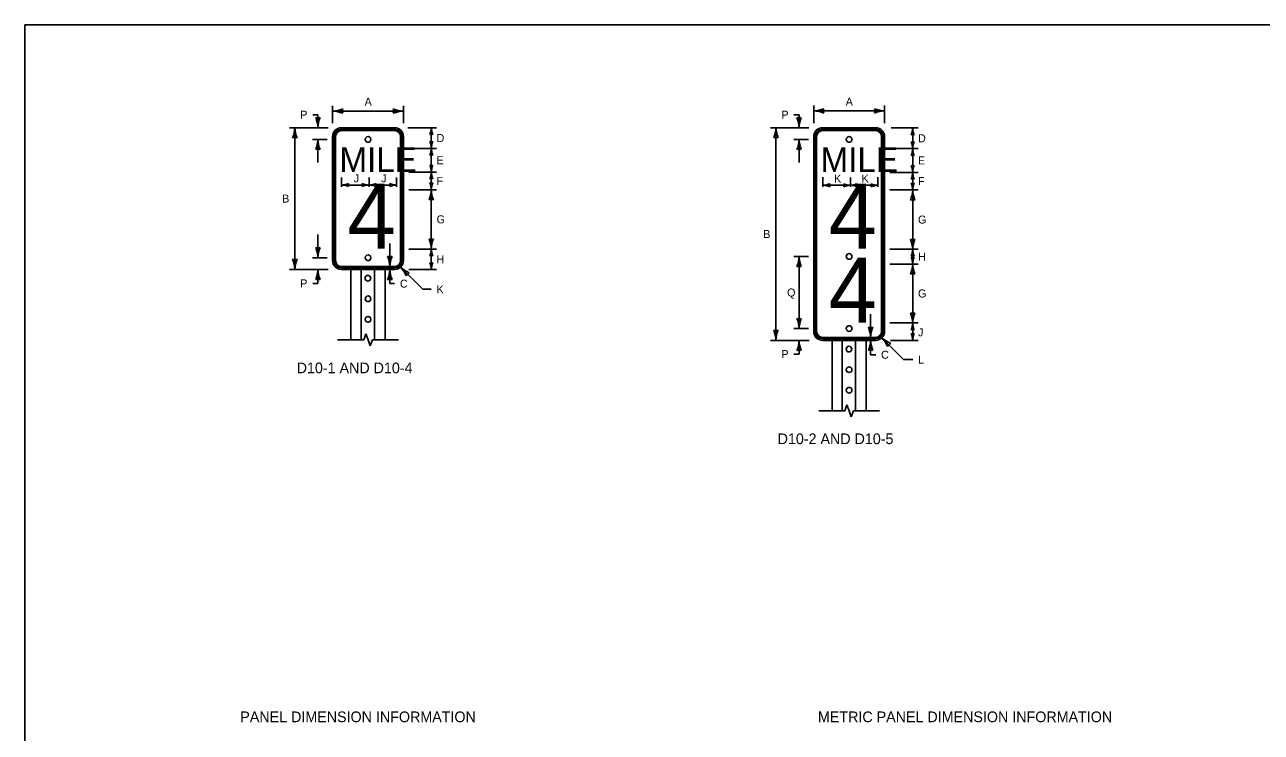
# Model space of a CAD drawing. Extents: x 49991.4 to 50021, y 49987.6 to 50011.4.
# Drawn here: x 49999.38 to 50008.65, y 49993.7 to 49999 of the extents above; entities that cross this region are included whole.
import ezdxf

# ---------------------------------------------------------------- set-up
doc = ezdxf.new("R2010")
doc.units = 0
for name, color, linetype in [('Default', 7, 'Continuous'), ('Level 1', 7, 'Continuous'), ('Level 2', 7, 'Continuous'), ('Level 3', 7, 'Continuous'), ('Level 6', 7, 'Continuous')]:
    doc.layers.add(name, color=color, linetype=linetype)

msp = doc.modelspace()

# ---------------------------------------------------------------- linework, layer by layer
at = {"layer": 'Default'}
msp.add_line((50005.8072, 49996.6522), (50005.8072, 49996.6522), dxfattribs=at)
at = {"layer": 'Level 1'}
for p, q in [((50001.6909, 49998.1614), (50001.6909, 49997.2318)), ((50001.7019, 49998.1614), (50001.7019, 49997.2318)), ((50001.713, 49998.1614), (50001.713, 49997.2318)), ((50001.7573, 49998.2278), (50002.1557, 49998.2278)), ((50002.1557, 49998.2167), (50001.7573, 49998.2167)), ((50002.1557, 49998.2057), (50001.7573, 49998.2057)), ((50002.1999, 49997.2318), (50002.1999, 49998.1614)), ((50002.211, 49997.2318), (50002.211, 49998.1614)), ((50002.2221, 49997.2318), (50002.2221, 49998.1614)), ((50005.2969, 49998.1614), (50005.2969, 49996.7006)), ((50005.308, 49998.1614), (50005.308, 49996.7006)), ((50005.319, 49996.7005), (50005.319, 49998.1614)), ((50005.7617, 49998.2278), (50005.3633, 49998.2278)), ((50005.7617, 49998.2168), (50005.3633, 49998.2168)), ((50005.3633, 49998.2056), (50005.7617, 49998.2056)), ((50005.806, 49998.1614), (50005.806, 49996.7005)), ((50005.817, 49996.7006), (50005.817, 49998.1614)), ((50005.8281, 49996.7006), (50005.8281, 49998.1614)), ((50001.7573, 49997.1875), (50002.1557, 49997.1875)), ((50001.7573, 49997.1764), (50002.1557, 49997.1764)), ((50001.7573, 49997.1654), (50002.1557, 49997.1654)), ((50001.8287, 49997.1654), (50001.8287, 49996.6377)), ((50001.9044, 49997.1654), (50001.9044, 49996.6377)), ((50002.0049, 49997.1654), (50002.0049, 49996.6377)), ((50002.0841, 49997.1654), (50002.0841, 49996.6377)), ((50005.7617, 49996.6563), (50005.3633, 49996.6563)), ((50005.3633, 49996.6453), (50005.7617, 49996.6453)), ((50005.3633, 49996.6342), (50005.7617, 49996.6342)), ((50005.4347, 49996.6342), (50005.4347, 49996.1065)), ((50005.5104, 49996.6342), (50005.5104, 49996.1065)), ((50005.6109, 49996.6342), (50005.6109, 49996.1065)), ((50005.6901, 49996.6342), (50005.6901, 49996.1065))]:
    msp.add_line(p, q, dxfattribs=at)
msp.add_lwpolyline([(49999.3835, 49998.9992), (50016.7501, 49998.9992), (50016.7501, 49987.7988), (49999.3835, 49987.7988)], close=True, dxfattribs=at)
for centre in [(50001.9564, 49998.1397), (50005.5624, 49998.1397), (50001.9564, 49997.2533), (50005.5624, 49997.2626), (50001.9552, 49997.0997), (50001.9564, 49996.9455), (50001.9564, 49996.7916), (50005.5625, 49996.7222), (50005.5612, 49996.5685), (50005.5624, 49996.4143), (50005.5624, 49996.2604)]:
    msp.add_circle(centre, 0.0213, dxfattribs=at)
for centre, radius, start, end in [((50001.7573, 49998.1614), 0.0664, 90, 180), ((50001.7573, 49998.1614), 0.0553, 90, 180), ((50001.7573, 49998.1614), 0.0443, 90, 180), ((50002.1557, 49998.1614), 0.0664, 0, 90), ((50002.1557, 49998.1614), 0.0553, 0, 90), ((50002.1557, 49998.1614), 0.0443, 0, 90), ((50005.3633, 49998.1614), 0.0664, 90, 180), ((50005.3633, 49998.1614), 0.0553, 90, 180), ((50005.3633, 49998.1614), 0.0443, 90, 180), ((50005.7617, 49998.1614), 0.0664, 0, 90), ((50005.7617, 49998.1614), 0.0553, 0, 90), ((50005.7617, 49998.1614), 0.0443, 0, 90), ((50001.7573, 49997.2318), 0.0664, 180, 270), ((50001.7573, 49997.2318), 0.0553, 180, 270), ((50001.7573, 49997.2318), 0.0443, 180, 270), ((50002.1557, 49997.2318), 0.0664, 270, 0), ((50002.1557, 49997.2318), 0.0553, 270, 0), ((50002.1557, 49997.2318), 0.0443, 270, 0), ((50005.3633, 49996.7006), 0.0664, 180, 270), ((50005.3633, 49996.7006), 0.0553, 180, 270), ((50005.3633, 49996.7006), 0.0443, 180, 270), ((50005.7617, 49996.7006), 0.0664, 270, 0), ((50005.7617, 49996.7006), 0.0553, 270, 0), ((50005.7617, 49996.7006), 0.0443, 270, 0)]:
    msp.add_arc(centre, radius, start, end, dxfattribs=at)
at = {"layer": 'Level 2'}
for p, q in [((50006.0386, 49998.226), (50006.0386, 49998.0708)), ((50006.0386, 49998.0708), (50006.0386, 49997.8931))]:
    msp.add_line(p, q, dxfattribs=at)
at = {"layer": 'Level 3'}
for p, q in [((50001.6908, 49998.2614), (50001.6908, 49998.3925)), ((50001.6908, 49998.3525), (50002.2221, 49998.3525)), ((50002.2221, 49998.2614), (50002.2221, 49998.3925)), ((50005.2969, 49998.2614), (50005.2969, 49998.3933)), ((50005.2969, 49998.3533), (50005.8281, 49998.3533)), ((50005.8281, 49998.2614), (50005.8281, 49998.3933)), ((50001.581, 49998.325), (50001.5423, 49998.325)), ((50001.581, 49998.325), (50001.581, 49998.2277)), ((50005.187, 49998.325), (50005.1483, 49998.325)), ((50005.187, 49998.325), (50005.187, 49998.2277)), ((50001.3681, 49998.2277), (50001.6573, 49998.2277)), ((50001.4081, 49998.2277), (50001.4081, 49997.1653)), ((50002.2557, 49998.2277), (50002.4705, 49998.2277)), ((50002.4305, 49998.2277), (50002.4305, 49998.0725)), ((50004.9741, 49998.2277), (50005.2593, 49998.2277)), ((50005.0141, 49998.2277), (50005.0141, 49996.6341)), ((50005.8771, 49998.226), (50006.0786, 49998.226)), ((50001.541, 49998.1397), (50001.6508, 49998.1397)), ((50001.581, 49998.1397), (50001.581, 49997.9663)), ((50002.2621, 49998.0725), (50002.4705, 49998.0725)), ((50002.4305, 49998.0725), (50002.4305, 49997.8948)), ((50005.147, 49998.1397), (50005.2569, 49998.1397)), ((50005.187, 49998.1397), (50005.187, 49997.9663)), ((50005.8681, 49998.0708), (50006.0786, 49998.0708)), ((50002.2621, 49997.8948), (50002.4705, 49997.8948)), ((50002.4305, 49997.8948), (50002.4305, 49997.7629)), ((50005.8681, 49997.8931), (50006.0786, 49997.8931)), ((50006.0386, 49997.8931), (50006.0386, 49997.7612)), ((50001.7582, 49997.8557), (50001.7582, 49997.7856)), ((50001.7582, 49997.7981), (50001.9813, 49997.7981)), ((50001.9643, 49997.8557), (50001.9643, 49997.7856)), ((50001.9813, 49997.7981), (50002.1703, 49997.7981)), ((50002.1703, 49997.8557), (50002.1703, 49997.7856)), ((50005.3663, 49997.8558), (50005.3663, 49997.7839)), ((50005.3663, 49997.854), (50005.3663, 49997.7839)), ((50005.3663, 49997.7964), (50005.5894, 49997.7964)), ((50005.3663, 49997.7964), (50005.5894, 49997.7964)), ((50005.5724, 49997.854), (50005.5724, 49997.7839)), ((50005.5894, 49997.7964), (50005.7784, 49997.7964)), ((50005.5894, 49997.7964), (50005.7784, 49997.7964)), ((50005.7784, 49997.8558), (50005.7784, 49997.7839)), ((50005.7784, 49997.854), (50005.7784, 49997.7839)), ((50002.2621, 49997.7629), (50002.4705, 49997.7629)), ((50002.4305, 49997.7629), (50002.4305, 49997.3186)), ((50005.8681, 49997.7612), (50006.0786, 49997.7612)), ((50006.0386, 49997.7612), (50006.0386, 49997.3169)), ((50001.581, 49997.2533), (50001.581, 49997.4268)), ((50002.1203, 49997.1875), (50002.1203, 49997.3609)), ((50001.541, 49997.2533), (50001.6508, 49997.2533)), ((50002.2621, 49997.3186), (50002.4705, 49997.3186)), ((50002.2981, 49997.3186), (50002.4665, 49997.3186)), ((50002.4305, 49997.3186), (50002.4305, 49997.1654)), ((50005.147, 49997.2626), (50005.2569, 49997.2626)), ((50005.187, 49997.2626), (50005.187, 49996.7222)), ((50005.8681, 49997.3169), (50006.0786, 49997.3169)), ((50006.0386, 49997.3169), (50006.0386, 49997.2061)), ((50001.3681, 49997.1653), (50001.6573, 49997.1653)), ((50001.581, 49997.1653), (50001.581, 49997.0611)), ((50002.1203, 49997.0591), (50002.1203, 49997.1654)), ((50002.2003, 49997.1825), (50002.3663, 49997.0165)), ((50002.2617, 49997.1654), (50002.4705, 49997.1654)), ((50005.8681, 49997.2061), (50006.0786, 49997.2061)), ((50006.0386, 49997.2061), (50006.0386, 49996.7645)), ((50001.581, 49997.0611), (50001.5423, 49997.0611)), ((50002.1203, 49997.0591), (50002.1557, 49997.0591)), ((50002.3663, 49997.0165), (50002.4305, 49997.0165)), ((50005.7236, 49996.6563), (50005.7236, 49996.8298)), ((50005.8681, 49996.7645), (50006.0786, 49996.7645)), ((50005.9042, 49996.7645), (50006.0746, 49996.7645)), ((50005.147, 49996.7222), (50005.2569, 49996.7222)), ((50006.0386, 49996.7542), (50006.0386, 49996.6342)), ((50004.9741, 49996.6341), (50005.2633, 49996.6342)), ((50005.187, 49996.6341), (50005.187, 49996.5312)), ((50005.7236, 49996.6342), (50005.7236, 49996.5262)), ((50005.8083, 49996.6533), (50005.9698, 49996.4896)), ((50005.8725, 49996.6342), (50006.0786, 49996.6342)), ((50005.187, 49996.5312), (50005.1483, 49996.5312)), ((50005.7236, 49996.5262), (50005.7617, 49996.5262)), ((50005.9698, 49996.4896), (50006.0386, 49996.4896))]:
    msp.add_line(p, q, dxfattribs=at)
for centre, radius, start, end in [((50001.6793, 49998.5852), 0.233, 272.82731, 292.07716), ((50001.6817, 49998.1304), 0.2223, 67.45601, 87.63952), ((50001.819, 49998.3525), 0.0548, 162.13882, 197.86118), ((50002.2313, 49998.5747), 0.2223, 247.45601, 267.63952), ((50002.0939, 49998.3525), 0.0548, 342.13882, 17.86118), ((50002.2336, 49998.1198), 0.233, 92.82731, 112.07716), ((50005.2854, 49998.586), 0.233, 272.82731, 292.07716), ((50005.2877, 49998.1312), 0.2223, 67.45601, 87.63952), ((50005.4251, 49998.3533), 0.0548, 162.13882, 197.86118), ((50005.8373, 49998.5755), 0.2223, 247.45601, 267.63952), ((50005.6999, 49998.3533), 0.0548, 342.13882, 17.86118), ((50005.8396, 49998.1206), 0.233, 92.82731, 112.07716), ((50001.581, 49998.3559), 0.0548, 252.13882, 287.86118), ((50001.3483, 49998.2162), 0.233, 2.82731, 22.07716), ((50001.8032, 49998.2186), 0.2223, 157.45601, 177.63952), ((50005.187, 49998.3559), 0.0548, 252.13882, 287.86118), ((50004.9543, 49998.2162), 0.233, 2.82731, 22.07716), ((50005.4091, 49998.2186), 0.2223, 157.45601, 177.63952), ((50001.186, 49998.2369), 0.2223, 337.45601, 357.63952), ((50001.4081, 49998.0995), 0.0548, 72.13882, 107.86118), ((50001.6408, 49998.2392), 0.233, 182.82731, 202.07716), ((50002.2824, 49998.2338), 0.1482, 337.45601, 357.63952), ((50002.4305, 49998.1423), 0.0365, 72.13882, 107.86118), ((50002.5857, 49998.2354), 0.1553, 182.82731, 202.07716), ((50004.792, 49998.2369), 0.2223, 337.45601, 357.63952), ((50005.0141, 49998.0995), 0.0548, 72.13882, 107.86118), ((50005.2468, 49998.2392), 0.233, 182.82731, 202.07716), ((50005.8905, 49998.2321), 0.1482, 337.45601, 357.63952), ((50006.0386, 49998.1406), 0.0365, 72.13882, 107.86118), ((50006.1938, 49998.2337), 0.1553, 182.82731, 202.07716), ((50001.3589, 49998.1489), 0.2223, 337.45601, 357.63952), ((50001.581, 49998.0115), 0.0548, 72.13882, 107.86118), ((50001.8137, 49998.1512), 0.233, 182.82731, 202.07716), ((50002.4305, 49998.158), 0.0365, 252.13882, 287.86118), ((50002.2754, 49998.0649), 0.1553, 2.82731, 22.07716), ((50002.2824, 49998.0786), 0.1482, 337.45601, 357.63952), ((50002.5786, 49998.0664), 0.1482, 157.45601, 177.63952), ((50002.5857, 49998.0802), 0.1553, 182.82731, 202.07716), ((50004.9649, 49998.1489), 0.2223, 337.45601, 357.63952), ((50005.187, 49998.0115), 0.0548, 72.13882, 107.86118), ((50005.4197, 49998.1512), 0.233, 182.82731, 202.07716), ((50006.0386, 49998.1563), 0.0365, 252.13882, 287.86118), ((50005.8835, 49998.0632), 0.1553, 2.82731, 22.07716), ((50005.8905, 49998.0769), 0.1482, 337.45601, 357.63952), ((50006.1867, 49998.0647), 0.1482, 157.45601, 177.63952), ((50006.1938, 49998.0785), 0.1553, 182.82731, 202.07716), ((50002.4305, 49997.9871), 0.0365, 72.13882, 107.86118), ((50006.0386, 49997.9854), 0.0365, 72.13882, 107.86118), ((50002.4305, 49997.9803), 0.0365, 252.13882, 287.86118), ((50002.2754, 49997.8872), 0.1553, 2.82731, 22.07716), ((50002.2824, 49997.9009), 0.1482, 337.45601, 357.63952), ((50002.5786, 49997.8887), 0.1482, 157.45601, 177.63952), ((50002.5857, 49997.9025), 0.1553, 182.82731, 202.07716), ((50006.0386, 49997.9786), 0.0365, 252.13882, 287.86118), ((50005.8835, 49997.8855), 0.1553, 2.82731, 22.07716), ((50005.8905, 49997.8992), 0.1482, 337.45601, 357.63952), ((50006.1867, 49997.887), 0.1482, 157.45601, 177.63952), ((50006.1938, 49997.9008), 0.1553, 182.82731, 202.07716), ((50001.7506, 49997.9533), 0.1553, 272.82731, 292.07716), ((50001.7521, 49997.65), 0.1482, 67.45601, 87.63952), ((50001.8437, 49997.7981), 0.0365, 162.13882, 197.86118), ((50001.9704, 49997.9462), 0.1482, 247.45601, 267.63952), ((50001.8788, 49997.7981), 0.0365, 342.13882, 17.86118), ((50001.9719, 49997.643), 0.1553, 92.82731, 112.07716), ((50001.9566, 49997.9533), 0.1553, 272.82731, 292.07716), ((50001.9582, 49997.65), 0.1482, 67.45601, 87.63952), ((50002.0498, 49997.7981), 0.0365, 162.13882, 197.86118), ((50002.1764, 49997.9462), 0.1482, 247.45601, 267.63952), ((50002.0849, 49997.7981), 0.0365, 342.13882, 17.86118), ((50002.178, 49997.643), 0.1553, 92.82731, 112.07716), ((50002.4305, 49997.8094), 0.0365, 72.13882, 107.86118), ((50002.4305, 49997.8484), 0.0365, 252.13882, 287.86118), ((50002.2754, 49997.7553), 0.1553, 2.82731, 22.07716), ((50002.5786, 49997.7568), 0.1482, 157.45601, 177.63952), ((50005.3587, 49997.9516), 0.1553, 272.82731, 292.07716), ((50005.3587, 49997.9516), 0.1553, 272.82731, 292.07716), ((50005.3602, 49997.6483), 0.1482, 67.45601, 87.63952), ((50005.3602, 49997.6483), 0.1482, 67.45601, 87.63952), ((50005.4518, 49997.7964), 0.0365, 162.13882, 197.86118), ((50005.4518, 49997.7964), 0.0365, 162.13882, 197.86118), ((50005.5785, 49997.9445), 0.1482, 247.45601, 267.63952), ((50005.4869, 49997.7964), 0.0365, 342.13882, 17.86118), ((50005.58, 49997.6413), 0.1553, 92.82731, 112.07716), ((50005.5647, 49997.9516), 0.1553, 272.82731, 292.07716), ((50005.5663, 49997.6483), 0.1482, 67.45601, 87.63952), ((50005.6578, 49997.7964), 0.0365, 162.13882, 197.86118), ((50005.7845, 49997.9445), 0.1482, 247.45601, 267.63952), ((50005.6929, 49997.7964), 0.0365, 342.13882, 17.86118), ((50005.7845, 49997.9445), 0.1482, 247.45601, 267.63952), ((50005.6929, 49997.7964), 0.0365, 342.13882, 17.86118), ((50005.7861, 49997.6413), 0.1553, 92.82731, 112.07716), ((50005.7861, 49997.6413), 0.1553, 92.82731, 112.07716), ((50006.0386, 49997.8077), 0.0365, 72.13882, 107.86118), ((50006.0386, 49997.8467), 0.0365, 252.13882, 287.86118), ((50005.8835, 49997.7536), 0.1553, 2.82731, 22.07716), ((50006.1867, 49997.7551), 0.1482, 157.45601, 177.63952), ((50002.2084, 49997.7721), 0.2223, 337.45601, 357.63952), ((50002.6632, 49997.7744), 0.233, 182.82731, 202.07716), ((50005.8165, 49997.7704), 0.2223, 337.45601, 357.63952), ((50006.2713, 49997.7727), 0.233, 182.82731, 202.07716), ((50002.4305, 49997.6347), 0.0548, 72.13882, 107.86118), ((50006.0386, 49997.633), 0.0548, 72.13882, 107.86118), ((50001.581, 49997.3815), 0.0548, 252.13882, 287.86118), ((50001.3483, 49997.2418), 0.233, 2.82731, 22.07716), ((50001.8032, 49997.2442), 0.2223, 157.45601, 177.63952), ((50002.4305, 49997.4468), 0.0548, 252.13882, 287.86118), ((50002.1978, 49997.3071), 0.233, 2.82731, 22.07716), ((50002.6527, 49997.3095), 0.2223, 157.45601, 177.63952), ((50006.0386, 49997.4451), 0.0548, 252.13882, 287.86118), ((50005.8059, 49997.3054), 0.233, 2.82731, 22.07716), ((50006.2607, 49997.3078), 0.2223, 157.45601, 177.63952), ((50001.4081, 49997.2935), 0.0548, 252.13882, 287.86118), ((50001.1754, 49997.1538), 0.233, 2.82731, 22.07716), ((50001.6303, 49997.1562), 0.2223, 157.45601, 177.63952), ((50002.1203, 49997.3157), 0.0548, 252.13882, 287.86118), ((50001.8876, 49997.176), 0.233, 2.82731, 22.07716), ((50002.3425, 49997.1783), 0.2223, 157.45601, 177.63952), ((50002.2824, 49997.3247), 0.1482, 337.45601, 357.63952), ((50002.4305, 49997.2332), 0.0365, 72.13882, 107.86118), ((50002.5857, 49997.3263), 0.1553, 182.82731, 202.07716), ((50004.9649, 49997.2718), 0.2223, 337.45601, 357.63952), ((50005.4197, 49997.2741), 0.233, 182.82731, 202.07716), ((50005.8905, 49997.323), 0.1482, 337.45601, 357.63952), ((50006.0386, 49997.2315), 0.0365, 72.13882, 107.86118), ((50006.0386, 49997.2916), 0.0365, 252.13882, 287.86118), ((50005.8835, 49997.1985), 0.1553, 2.82731, 22.07716), ((50006.1938, 49997.3246), 0.1553, 182.82731, 202.07716), ((50006.1867, 49997.2), 0.1482, 157.45601, 177.63952), ((50001.3589, 49997.1745), 0.2223, 337.45601, 357.63952), ((50001.8137, 49997.1768), 0.233, 182.82731, 202.07716), ((50001.8982, 49997.1745), 0.2223, 337.45601, 357.63952), ((50002.353, 49997.1768), 0.233, 182.82731, 202.07716), ((50002.0367, 49997.032), 0.2223, 22.45601, 42.63952), ((50002.3567, 49997.3552), 0.233, 227.82731, 247.07716), ((50002.2909, 49997.0919), 0.0548, 117.13882, 152.86118), ((50002.4305, 49997.2508), 0.0365, 252.13882, 287.86118), ((50002.2754, 49997.1577), 0.1553, 2.82731, 22.07716), ((50002.5786, 49997.1592), 0.1482, 157.45601, 177.63952), ((50005.187, 49997.1344), 0.0548, 72.13882, 107.86118), ((50005.8165, 49997.2153), 0.2223, 337.45601, 357.63952), ((50006.2713, 49997.2176), 0.233, 182.82731, 202.07716), ((50001.581, 49997.0371), 0.0548, 72.13882, 107.86118), ((50002.1203, 49997.0371), 0.0548, 72.13882, 107.86118), ((50006.0386, 49997.0779), 0.0548, 72.13882, 107.86118), ((50005.187, 49996.8504), 0.0548, 252.13882, 287.86118), ((50004.9543, 49996.7107), 0.233, 2.82731, 22.07716), ((50005.4091, 49996.7131), 0.2223, 157.45601, 177.63952), ((50006.0386, 49996.8927), 0.0548, 252.13882, 287.86118), ((50005.8059, 49996.753), 0.233, 2.82731, 22.07716), ((50005.8905, 49996.7706), 0.1482, 337.45601, 357.63952), ((50006.2607, 49996.7554), 0.2223, 157.45601, 177.63952), ((50006.1938, 49996.7722), 0.1553, 182.82731, 202.07716), ((50005.0141, 49996.7623), 0.0548, 252.13882, 287.86118), ((50004.7814, 49996.6226), 0.233, 2.82731, 22.07716), ((50005.2362, 49996.625), 0.2223, 157.45601, 177.63952), ((50005.7236, 49996.7845), 0.0548, 252.13882, 287.86118), ((50005.4909, 49996.6448), 0.233, 2.82731, 22.07716), ((50005.9457, 49996.6472), 0.2223, 157.45601, 177.63952), ((50006.0386, 49996.6791), 0.0365, 72.13882, 107.86118), ((50006.0386, 49996.7197), 0.0365, 252.13882, 287.86118), ((50005.8835, 49996.6265), 0.1553, 2.82731, 22.07716), ((50006.1867, 49996.6281), 0.1482, 157.45601, 177.63952), ((50004.9649, 49996.6433), 0.2223, 337.45601, 357.63952), ((50005.4197, 49996.6456), 0.233, 182.82731, 202.07716), ((50005.5015, 49996.6434), 0.2223, 337.45601, 357.63952), ((50005.9563, 49996.6457), 0.233, 182.82731, 202.07716), ((50005.6448, 49996.5027), 0.2223, 22.45601, 42.63952), ((50005.9648, 49996.826), 0.233, 227.82731, 247.07716), ((50005.899, 49996.5627), 0.0548, 117.13882, 152.86118), ((50005.187, 49996.5059), 0.0548, 72.13882, 107.86118), ((50005.7236, 49996.506), 0.0548, 72.13882, 107.86118)]:
    msp.add_arc(centre, radius, start, end, dxfattribs=at)
at = {"layer": 'Level 6'}
for p, q in [((50001.9402, 49996.6834), (50001.924, 49996.6377)), ((50001.9402, 49996.6834), (50001.9564, 49996.6377)), ((50001.7287, 49996.6377), (50001.924, 49996.6377)), ((50001.9564, 49996.6377), (50001.9726, 49996.592)), ((50001.9888, 49996.6377), (50001.9726, 49996.592)), ((50001.9888, 49996.6377), (50002.1841, 49996.6377)), ((50005.5462, 49996.1522), (50005.53, 49996.1065)), ((50005.5462, 49996.1522), (50005.5624, 49996.1065)), ((50005.3347, 49996.1065), (50005.53, 49996.1065)), ((50005.5624, 49996.1065), (50005.5786, 49996.0608)), ((50005.5948, 49996.1065), (50005.5786, 49996.0608)), ((50005.5948, 49996.1065), (50005.7901, 49996.1065))]:
    msp.add_line(p, q, dxfattribs=at)

# ---------------------------------------------------------------- texts
at = {"layer": 'Level 1'}
for s, height, p in [('MILE', 0.186, (50001.7419, 49997.8957)), ('MILE', 0.1859, (50005.3479, 49997.8958)), ('4', 0.487, (50001.8022, 49997.3202)), ('4', 0.4869, (50005.4082, 49997.3203)), ('4', 0.4869, (50005.4082, 49996.767))]:
    msp.add_text(s, height=height, dxfattribs=at).set_placement(p)
at = {"layer": 'Level 2'}
for s, height, p in [('A', 0.06, (50001.9308, 49998.3925)), ('A', 0.06, (50005.5367, 49998.3933)), ('P', 0.06, (50001.4487, 49998.295)), ('P', 0.06, (50005.0547, 49998.295)), ('D', 0.06, (50002.4705, 49998.1201)), ('D', 0.06, (50006.0786, 49998.1184)), ('E', 0.06, (50002.4705, 49997.9536)), ('E', 0.06, (50006.0786, 49997.952)), ('J', 0.06, (50001.8494, 49997.8181)), ('J', 0.06, (50002.0555, 49997.8181)), ('K', 0.06, (50005.4498, 49997.8164)), ('K', 0.06, (50005.6558, 49997.8164)), ('F', 0.06, (50002.4705, 49997.7988)), ('F', 0.06, (50006.0786, 49997.7972)), ('B', 0.06, (50001.3126, 49997.6665)), ('G', 0.06, (50002.4705, 49997.5108)), ('G', 0.06, (50006.0786, 49997.509)), ('B', 0.06, (50004.9186, 49997.4009)), ('H', 0.06, (50002.4705, 49997.212)), ('H', 0.06, (50006.0786, 49997.2315)), ('P', 0.06, (50001.4487, 49997.0311)), ('C', 0.06, (50002.1957, 49997.0291)), ('K', 0.06, (50002.4705, 49996.9865)), ('Q', 0.06, (50005.0976, 49996.9624)), ('G', 0.06, (50006.0786, 49996.9553)), ('J', 0.06, (50006.0786, 49996.6642)), ('P', 0.06, (50005.0547, 49996.5012)), ('C', 0.06, (50005.8017, 49996.4962)), ('L', 0.06, (50006.0786, 49996.4596)), ('D10-1 AND D10-4', 0.08, (50001.4217, 49996.3877)), ('D10-2 AND D10-5', 0.08, (50005.0265, 49995.8565)), ('PANEL DIMENSION INFORMATION', 0.08, (50000.9992, 49993.773)), ('METRIC PANEL DIMENSION INFORMATION', 0.08, (50005.3288, 49993.773))]:
    msp.add_text(s, height=height, dxfattribs=at).set_placement(p)

doc.saveas('drawing.dxf')
